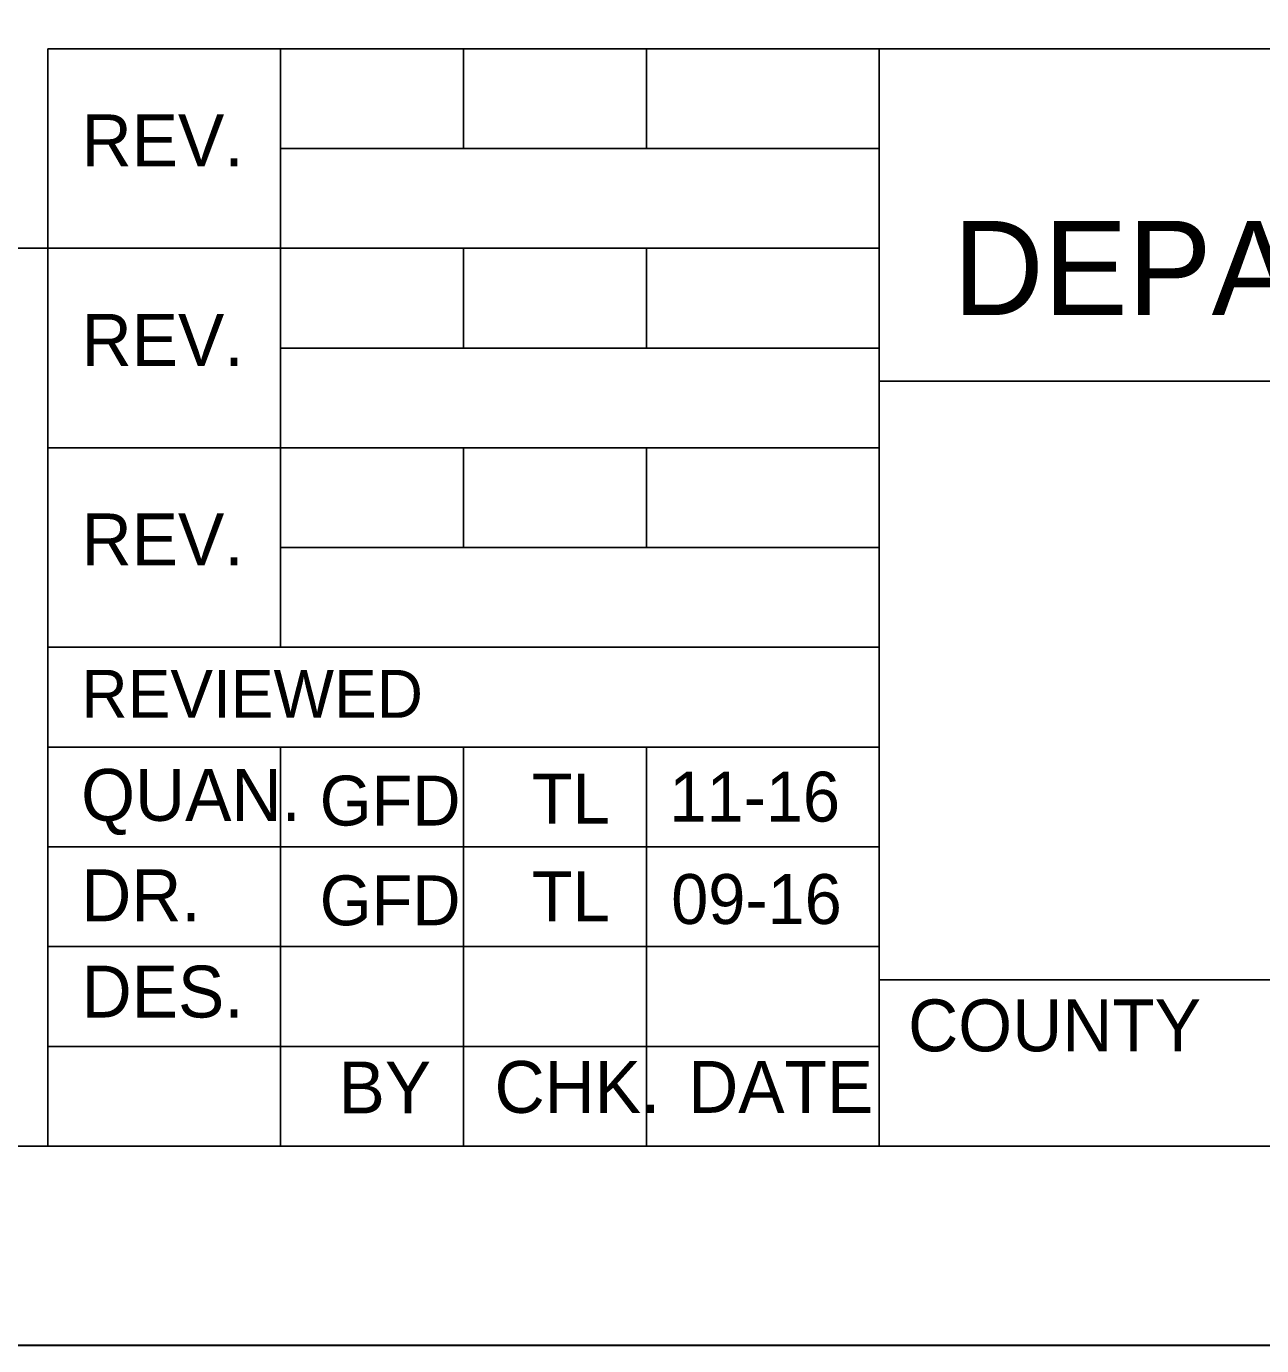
# Model space of a CAD drawing. Extents: x 1334.3 to 1370.4, y 717.9 to 739.9.
# Drawn here: x 1362.28 to 1365.376, y 717.865 to 721.171 of the extents above; entities that cross this region are included whole.
import ezdxf

# ---------------------------------------------------------------- set-up
doc = ezdxf.new("R2010")
doc.units = 0
for name, color, linetype in [('BR_BORDER LINES', 7, 'Continuous'), ('BR_TEXT', 7, 'Continuous'), ('RD_SHT_IplotShp', 7, 'Continuous')]:
    doc.layers.add(name, color=color, linetype=linetype)

msp = doc.modelspace()

# ---------------------------------------------------------------- linework, layer by layer
at = {"layer": 'BR_BORDER LINES'}
for p, q in [((1362.3339, 718.3649), (1362.3339, 721.1149)), ((1362.3339, 721.1149), (1369.8339, 721.1149)), ((1362.9173, 721.1149), (1362.9173, 719.6149)), ((1363.3756, 720.8649), (1363.3756, 721.1149)), ((1363.8339, 720.8649), (1363.8339, 721.1149)), ((1364.4173, 718.3649), (1364.4173, 721.1149)), ((1362.9173, 720.8649), (1364.4173, 720.8649)), ((1360.0214, 720.6149), (1362.3339, 720.6149)), ((1362.3339, 720.6149), (1364.4173, 720.6149)), ((1363.3756, 720.3649), (1363.3756, 720.6149)), ((1363.8339, 720.3649), (1363.8339, 720.6149)), ((1362.9173, 720.3649), (1364.4173, 720.3649)), ((1364.4173, 720.2815), (1369.8339, 720.2815)), ((1364.4173, 720.2815), (1364.4173, 720.2815)), ((1362.3339, 720.1149), (1364.4173, 720.1149)), ((1363.3756, 719.8649), (1363.3756, 720.1149)), ((1363.8339, 719.8649), (1363.8339, 720.1149)), ((1362.9173, 719.8649), (1364.4173, 719.8649)), ((1362.3339, 719.6149), (1364.4173, 719.6149)), ((1362.3339, 719.3649), (1364.4173, 719.3649)), ((1362.9173, 719.3649), (1362.9173, 718.3649)), ((1363.3756, 719.3649), (1363.3756, 718.3649)), ((1363.8339, 719.3649), (1363.8339, 718.3649)), ((1362.3339, 719.1149), (1364.4173, 719.1149)), ((1362.3339, 718.8649), (1364.4173, 718.8649)), ((1364.4173, 718.7815), (1369.8339, 718.7815)), ((1362.3339, 718.6149), (1364.4173, 718.6149)), ((1336.1673, 718.3649), (1369.8339, 718.3649)), ((1334.334, 717.8663), (1370.334, 717.8663))]:
    msp.add_line(p, q, dxfattribs=at)
at = {"layer": 'RD_SHT_IplotShp'}
msp.add_lwpolyline([(1334.334, 739.8649), (1370.334, 739.8649), (1370.334, 717.8649), (1334.334, 717.8649)], close=True, dxfattribs=at)

# ---------------------------------------------------------------- texts
at = {"layer": 'BR_TEXT'}
for s, height, p in [('REV.', 0.13, (1362.4186, 720.8203)), ('DEPARTMENT  OF  TRANSPORTATION', 0.235852, (1364.6021, 720.4477)), ('REV.', 0.13, (1362.4186, 720.3203)), ('REV.', 0.13, (1362.4186, 719.8203)), ('REVIEWED', 0.12, (1362.418, 719.4384)), ('QUAN.', 0.13, (1362.4173, 719.18)), ('11-16', 0.125, (1363.8916, 719.1782)), ('GFD', 0.125, (1363.0153, 719.1683)), ('TL', 0.125, (1363.547, 719.1733)), ('DR.', 0.13, (1362.4175, 718.9285)), ('GFD', 0.125, (1363.0153, 718.9183)), ('TL', 0.125, (1363.547, 718.9283)), ('09-16', 0.125, (1363.8961, 718.9216)), ('DES.', 0.13, (1362.4186, 718.6872)), ('COUNTY', 0.13, (1364.4898, 718.6024)), ('CHK.', 0.13, (1363.4534, 718.4482)), ('DATE', 0.13, (1363.9386, 718.4483)), ('BY', 0.13, (1363.0626, 718.4469))]:
    msp.add_text(s, height=height, dxfattribs=at).set_placement(p)

doc.saveas('drawing.dxf')
